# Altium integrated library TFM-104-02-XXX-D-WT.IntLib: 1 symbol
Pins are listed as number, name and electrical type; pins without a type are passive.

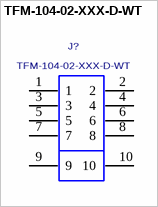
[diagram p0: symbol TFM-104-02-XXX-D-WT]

## TFM-104-02-XXX-D-WT
designator J?
0.050" TERMINAL STRIP, SURFACE MOUNT ASSEMBLY.; MANUFACTURER: SAMTEC
footprint TFM-104-02-XXX-D-WT
pins: 1, 2, 3, 4, 5, 6, 7, 8, 9, 10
